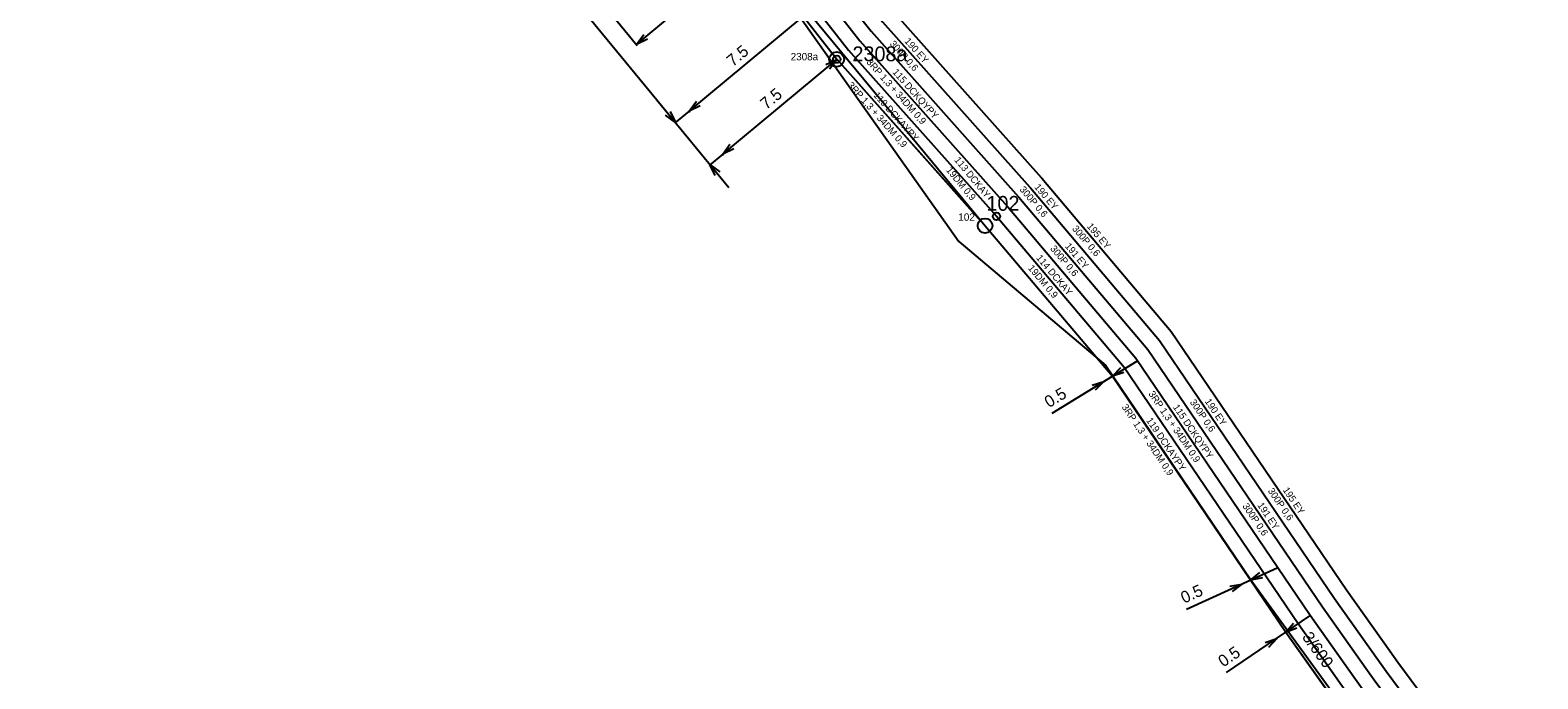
# Model space of a CAD drawing. Extents: x -756413 to -755757, y -1139003 to -1138237.
# Drawn here: x -756232.5 to -756156, y -1138380.6 to -1138347.7 of the extents above; entities that cross this region are included whole.
import ezdxf

# ---------------------------------------------------------------- set-up
doc = ezdxf.new("R2010")
doc.units = 0
for name, color, linetype in [('f004_popis_kab_zil', 7, 'Continuous'), ('f004_popisy_mts', 7, 'Continuous'), ('f004_rezervy_spojky', 7, 'Continuous'), ('f006_osa_trasy', 7, 'Continuous'), ('f006_stp_koty', 7, 'Continuous'), ('f307_kabel_metal', 7, 'Continuous'), ('f307_kabel_metal_ann', 7, 'Continuous'), ('f307_spojka_metal', 7, 'Continuous'), ('f307_spojka_metal_ann', 7, 'Continuous')]:
    doc.layers.add(name, color=color, linetype=linetype)

msp = doc.modelspace()

# ---------------------------------------------------------------- linework, layer by layer
at = {"layer": 'f004_rezervy_spojky'}
for centre in [(-756191.54, -1138349.16), (-756184.01, -1138357.6)]:
    msp.add_circle(centre, 0.375, dxfattribs=at)
at = {"layer": 'f006_osa_trasy'}
for p, q in [((-756204.84, -1138332.43), (-756184.01, -1138357.6)), ((-756193.24, -1138346.98), (-756191.54, -1138349.16)), ((-756191.54, -1138349.16), (-756184.01, -1138357.6))]:
    msp.add_line(p, q, dxfattribs=at)
for points in [[(-756195.84, -1138343.55), (-756185.35, -1138358.4), (-756177.88, -1138364.69), (-756170.53, -1138375.55), (-756161.61, -1138387.83), (-756142.93, -1138413.51), (-756121.74, -1138435.57), (-756109.6, -1138449.6), (-756100.9, -1138454.08), (-756099.19, -1138454.87), (-756076.56, -1138471.66)], [(-756184.01, -1138357.6), (-756177.55, -1138365.23), (-756168.74, -1138378.2), (-756166.27, -1138381.69)]]:
    msp.add_lwpolyline(points, dxfattribs=at)
at = {"layer": 'f006_stp_koty'}
for p, q in [((-756211.599, -1138337.907), (-756199.728, -1138352.364)), ((-756201.698, -1138348.408), (-756195.837, -1138343.545)), ((-756202.916, -1138346.94), (-756201.66, -1138348.454)), ((-756199.025, -1138351.788), (-756193.236, -1138346.984)), ((-756197.325, -1138353.968), (-756191.536, -1138349.164)), ((-756191.551, -1138349.146), (-756191.498, -1138349.21)), ((-756200.68, -1138351.205), (-756197.022, -1138355.659)), ((-756199.026, -1138351.788), (-756199.774, -1138352.402)), ((-756199.026, -1138351.788), (-756199.774, -1138352.402)), ((-756199.025, -1138351.788), (-756198.987, -1138351.834)), ((-756197.326, -1138353.968), (-756198.02, -1138354.538)), ((-756197.325, -1138353.968), (-756197.287, -1138354.014)), ((-756180.61, -1138367.108), (-756176.271, -1138364.445)), ((-756173.785, -1138377.041), (-756169.18, -1138374.948)), ((-756171.75, -1138380.252), (-756167.53, -1138377.374))]:
    msp.add_line(p, q, dxfattribs=at)
for points in [[(-756201.14, -1138348.14), (-756201.698, -1138348.408), (-756201.331, -1138347.909)], [(-756192.093, -1138349.431), (-756191.536, -1138349.164), (-756191.901, -1138349.662)], [(-756198.467, -1138351.52), (-756199.025, -1138351.788), (-756198.659, -1138351.289)], [(-756199.992, -1138351.805), (-756199.728, -1138352.364), (-756200.224, -1138351.995)], [(-756199.992, -1138351.805), (-756199.728, -1138352.364), (-756200.224, -1138351.995)], [(-756196.767, -1138353.7), (-756197.325, -1138353.968), (-756196.959, -1138353.469)], [(-756197.709, -1138355.058), (-756197.974, -1138354.5), (-756197.477, -1138354.868)], [(-756176.96, -1138365.044), (-756177.55, -1138365.23), (-756177.117, -1138364.788)], [(-756178.579, -1138365.685), (-756177.99, -1138365.5), (-756178.422, -1138365.941)], [(-756171.593, -1138375.88), (-756170.985, -1138375.769), (-756171.469, -1138376.153)], [(-756169.936, -1138375.457), (-756170.545, -1138375.569), (-756170.06, -1138375.184)], [(-756168.189, -1138378.005), (-756168.77, -1138378.22), (-756168.358, -1138377.758)], [(-756169.79, -1138378.734), (-756169.21, -1138378.52), (-756169.621, -1138378.981)]]:
    msp.add_lwpolyline(points, dxfattribs=at)
at = {"layer": 'f307_kabel_metal'}
for points in [[(-756270.019, -1138306.197), (-756266.653, -1138308.817), (-756266.11, -1138309.24), (-756262.64, -1138315.59), (-756261.9, -1138316.99), (-756259.83, -1138323.74), (-756255.203, -1138328.655), (-756254.69, -1138329.2), (-756254.31, -1138329.67), (-756251.17, -1138328.82), (-756246.873, -1138326.389), (-756246.22, -1138326.02), (-756236.07, -1138320.55), (-756229.85, -1138314.13), (-756227.1, -1138311.3), (-756223.6, -1138309.06), (-756219.89, -1138313.31), (-756204.84, -1138332.43), (-756204.754, -1138332.538), (-756193.708, -1138346.394), (-756193.24, -1138346.98), (-756191.54, -1138349.16)], [(-756261.252, -1138316.611), (-756261.204, -1138316.702), (-756259.164, -1138323.353), (-756254.657, -1138328.141), (-756254.125, -1138328.707), (-756254.034, -1138328.818), (-756251.457, -1138328.121), (-756247.242, -1138325.736), (-756246.582, -1138325.363), (-756236.528, -1138319.945), (-756230.388, -1138313.608), (-756227.577, -1138310.715), (-756223.46, -1138308.08), (-756219.312, -1138312.831), (-756204.252, -1138331.964), (-756204.167, -1138332.071), (-756193.122, -1138345.926), (-756192.651, -1138346.515), (-756190.949, -1138348.699), (-756183.432, -1138357.122)], [(-756197.246, -1138338.346), (-756191.95, -1138344.99), (-756191.515, -1138345.534), (-756191.053, -1138346.124), (-756189.797, -1138347.737), (-756182.307, -1138356.129), (-756182.289, -1138356.151), (-756175.756, -1138363.868), (-756166.892, -1138376.919), (-756164.688, -1138380.032), (-756164.264, -1138380.619), (-756160.419, -1138385.809), (-756134.721, -1138415.912)], [(-756195.015, -1138339.942), (-756191.364, -1138344.522), (-756190.927, -1138345.069), (-756190.462, -1138345.662), (-756189.221, -1138347.256), (-756181.737, -1138355.642), (-756181.713, -1138355.671), (-756175.158, -1138363.414), (-756166.276, -1138376.492), (-756164.078, -1138379.596), (-756163.659, -1138380.176), (-756159.832, -1138385.342), (-756134.151, -1138415.425)], [(-756192.296, -1138342.149), (-756190.778, -1138344.054), (-756190.339, -1138344.604), (-756189.871, -1138345.2), (-756188.645, -1138346.775), (-756181.168, -1138355.153), (-756181.138, -1138355.19), (-756174.56, -1138362.96), (-756165.66, -1138376.065), (-756163.468, -1138379.16), (-756163.054, -1138379.733), (-756159.245, -1138384.875), (-756133.581, -1138414.937)], [(-756192.101, -1138346.002), (-756192.062, -1138346.05), (-756190.373, -1138348.218), (-756182.872, -1138356.623), (-756182.86, -1138356.637), (-756176.354, -1138364.322), (-756167.508, -1138377.346), (-756165.298, -1138380.468), (-756164.869, -1138381.062), (-756161.006, -1138386.276), (-756135.291, -1138416.4), (-756134.804, -1138416.968), (-756118.54, -1138435.935), (-756118.06, -1138436.494)], [(-756191.54, -1138349.16), (-756184.509, -1138357.041), (-756184.01, -1138357.6), (-756177.55, -1138365.23), (-756168.74, -1138378.2), (-756166.518, -1138381.34), (-756166.079, -1138381.948), (-756162.18, -1138387.21), (-756136.431, -1138417.375), (-756135.943, -1138417.944), (-756119.678, -1138436.911), (-756119.19, -1138437.48), (-756115.87, -1138441.22)], [(-756183.432, -1138357.122), (-756176.952, -1138364.776), (-756168.124, -1138377.773), (-756165.908, -1138380.904), (-756165.474, -1138381.505), (-756161.593, -1138386.743), (-756135.861, -1138416.887), (-756135.374, -1138417.456), (-756119.109, -1138436.423), (-756118.625, -1138436.987), (-756116.412, -1138439.48), (-756117.75, -1138440.561), (-756109.723, -1138449.702)]]:
    msp.add_lwpolyline(points, dxfattribs=at)
at = {"layer": 'f307_spojka_metal'}
for centre in [(-756191.54, -1138349.16), (-756183.432, -1138357.122)]:
    msp.add_circle(centre, 0.188, dxfattribs=at)

# ---------------------------------------------------------------- texts
at = {"layer": 'f004_popis_kab_zil'}
msp.add_text('3/600', height=0.6, rotation=305.99, dxfattribs=at).set_placement((-756167.95, -1138378.46))
at = {"layer": 'f004_popisy_mts'}
for s, p in [('2308a', (-756190.74, -1138349.26)), ('102', (-756183.94, -1138356.84))]:
    msp.add_text(s, height=0.75, dxfattribs=at).set_placement(p)
at = {"layer": 'f006_stp_koty'}
for s, rotation, p in [('7.5', 39.69, (-756196.812, -1138349.562)), ('7.5', 39.69, (-756195.112, -1138351.742)), ('0.5', 31.53, (-756180.766, -1138366.852)), ('0.5', 24.44, (-756173.909, -1138376.767)), ('0.5', 34.29, (-756171.919, -1138380.004))]:
    msp.add_text(s, height=0.6, rotation=rotation, dxfattribs=at).set_placement(p)
at = {"layer": 'f307_kabel_metal_ann'}
for s, rotation, p in [(' 300P 0,6', 311.75, (-756188.958, -1138348.302)), ('190 EY', 311.75, (-756188.125, -1138348.259)), (' 3RP 1,3 + 34DM 0,9', 311.75, (-756190.144, -1138349.225)), ('115 DCKQYPY', 311.75, (-756188.733, -1138349.829)), (' 3RP 1,3 + 34DM 0,9', 311.74, (-756191.104, -1138350.4)), ('119 DCKAYPY', 311.74, (-756189.694, -1138351.004)), ('113 DCKAY', 309.61, (-756185.589, -1138354.28)), (' 19DM 0,9', 309.61, (-756186.09, -1138354.693)), (' 300P 0,6', 310.25, (-756182.364, -1138355.676)), ('190 EY', 310.25, (-756181.53, -1138355.654)), (' 300P 0,6', 310.25, (-756179.699, -1138357.664)), ('195 EY', 310.25, (-756178.865, -1138357.642)), (' 300P 0,6', 310.25, (-756180.81, -1138358.673)), ('191 EY', 310.25, (-756179.976, -1138358.651)), (' 19DM 0,9', 310.25, (-756181.936, -1138359.664)), ('114 DCKAY', 310.25, (-756181.439, -1138359.245)), (' 3RP 1,3 + 34DM 0,9', 304.18, (-756175.808, -1138366.015)), (' 300P 0,6', 304.18, (-756173.707, -1138366.439)), ('190 EY', 304.18, (-756172.876, -1138366.506)), (' 3RP 1,3 + 34DM 0,9', 304.19, (-756177.166, -1138366.685)), ('119 DCKAYPY', 304.19, (-756175.847, -1138367.47)), ('115 DCKQYPY', 304.18, (-756174.489, -1138366.8)), (' 300P 0,6', 304.18, (-756169.748, -1138370.935)), ('195 EY', 304.18, (-756168.917, -1138371.002)), (' 300P 0,6', 304.18, (-756171.037, -1138371.705)), ('191 EY', 304.18, (-756170.206, -1138371.772))]:
    msp.add_text(s, height=0.35, rotation=rotation, dxfattribs=at).set_placement(p)
at = {"layer": 'f307_spojka_metal_ann'}
for s, p in [('2308a', (-756193.876, -1138349.213)), ('102', (-756185.367, -1138357.347))]:
    msp.add_text(s, height=0.375, dxfattribs=at).set_placement(p)

doc.saveas('drawing.dxf')
